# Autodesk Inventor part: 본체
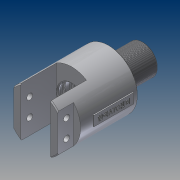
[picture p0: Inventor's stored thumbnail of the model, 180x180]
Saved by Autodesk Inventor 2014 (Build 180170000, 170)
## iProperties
Created: 2019-02
Part Number: 본체
Material: 알루미늄 6061
Document SubType Name: Modeling
Designer: 603-18
Density: 2.71 g/cm^3
Appearance: 알루미늄 - 평지
Mass: 344.106 g
Surface Area: 281.944 cm^2
Volume: 126.976 cm^3
Author: 603-18
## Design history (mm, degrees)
sketch "스케치1"
  geometry: L1 (-37, 0)-(37, 0); L2 (-37, 0)-(-37, 22); L3 (-1, 29)-(37, 29); L4 (37, 29)-(37, 0); L5 (26, 0)-(26, 16); L6 (26, 16)-(19, 16); L7 (19, 16)-(19, 14); L8 (19, 14)-(15.35, 14); L9 (15.35, 14)-(15.35, 15.2); L10 (14.55, 16)-(11.45, 16); L11 (10.65, 15.2)-(10.65, 14); L12 (10.65, 14)-(6.35, 14); L13 (5.55, 16)-(2.45, 16); L14 (1.65, 15.2)-(1.65, 14); L15 (1.65, 14)-(-1, 14); L16 (-1, 14)-(-1, 0); L17 (6.35, 14)-(6.35, 15.2); L18 (-1, 29)-(-37, 29); L19 (-37, 29)-(-37, 22); A1 r 0.8 centre (2.45, 15.2) between (2.45, 16) and (1.65, 15.2); A2 r 0.8 centre (5.55, 15.2) between (6.35, 15.2) and (5.55, 16); A3 r 0.8 centre (11.45, 15.2) between (11.45, 16) and (10.65, 15.2); A4 r 0.8 centre (14.55, 15.2) between (15.35, 15.2) and (14.55, 16); 5 further points
  constraints: 38 end point, 11 parallel, 8 point on circle, 8 tangent, 5 perpendicular, 4 centre point, 4 horizontal alignment, 4 midpoint, 3 equal radius, 2 point on line, 1 coincident, 1 collinear, 1 horizontal
  dimensions: "d0" = 74 distance of L1.start L1.end; "d1" = 20 distance between parallel lines of L16 L7; "d2" = 27 distance between parallel lines of L16 L5; "d3" = 28 diameter of L15 L1; "d5" = 58 diameter of L3 L1; "d6" = 4.7 distance between parallel lines of L17 L14; "d7" = 4.7 distance between parallel lines of L9 L11; "d9" = 7 distance between parallel lines of L5 L7 (derived); "d10" = 32 diameter of L6 L1; "d11" = 5 distance from line of L16 point (4, 16); "d12" = 9 distance of point (13, 16) point (4, 16); "d13" = 0.8 radius of A1; "d42" = 36 distance between parallel lines of L2 L16
revolve "회전1" stored, may be unused: angle "d15" = 90 deg
sketch "스케치4"
  geometry: C1 r 29 at (0, 0) reference; C2 r 14 at (0, 0)
  constraints: 1 centre point, 1 coincident
  dimensions: "d22" = 28 diameter of C2
extrude "돌출2" join sketch "스케치4" distance "d23" = 5; taper "d24" = 0 deg
sketch "스케치5"
  geometry: C1 r 14 at (0, 0) reference; C2 r 15 at (0, 0)
  constraints: 1 centre point, 1 coincident
  dimensions: "d25" = 30 diameter of C2
extrude "돌출3" join sketch "스케치5" distance "d26" = 29; taper "d27" = 0 deg
feature "스레드1" dims "d28" = 10, "d29" = 0
sketch "스케치6"
  geometry: C1 r 15 at (0, 0) reference
hole "구멍1" diameter "d32" = 12.376; stored, may be unused: countersink angle "d36" = 90 deg, drill point angle "d38" = 118 deg; dims "d30" = 10, "d31" = 10, "d33" = 18, "d34" = 4, "d35" = 2, "d37" = 22
sketch "스케치7"
  geometry: C1 r 16 at (0, 0) reference; C2 r 4 at (0, 0)
  constraints: 1 centre point, 1 coincident
  dimensions: "d39" = 8 diameter of C2
extrude "돌출4" cut sketch "스케치7" stored distance "d40" = 22; taper "d41" = 0 deg
sketch "스케치8"
  geometry: C1 r 29 at (0, 0) reference; C2 r 15 at (0, 0)
  constraints: 1 centre point, 1 coincident
  dimensions: "d43" = 30 diameter of C2
extrude "돌출5" cut sketch "스케치8" distance "d44" = 36; taper "d45" = 0 deg
sketch "스케치9"
  geometry: L1 (-22, 18.894)-(-22, -18.894); L2 (22, 18.894)-(22, -18.894); L3 (-15, 24.819)-(-15, -24.819); L4 (15, 24.819)-(15, -24.819); C1 r 15 at (0, 0) reference; A1 r 29 centre (0, 0) between (22, 18.894) and (-22, 18.894); A2 r 29 centre (0, 0) between (-22, -18.894) and (22, -18.894); A3 r 29 centre (0, 0) between (-22, 18.894) and (-22, -18.894); A4 r 29 centre (0, 0) between (22, -18.894) and (22, 18.894); 1 further point
  constraints: 12 point on circle, 8 end point, 4 centre point, 4 concentric, 3 vertical, 1 parallel, 10 other
  dimensions: "d46" = 22 distance from line of L2 C1.centre; "d47" = 22 distance from line of L1 C1.centre; "d48" = 15 distance from line of L4 C1.centre; "d49" = 15 distance from line of L3 C1.centre
extrude "돌출6" cut sketch "스케치9" distance "d50" = 36; taper "d51" = 0 deg
extrude "돌출7" cut sketch "스케치9" distance "d52" = 16; taper "d53" = 0 deg
sketch "스케치10"
  geometry: L1 (0, 0)-(0, 37.789) reference; L2 (0, 37.789)-(16, 37.789) reference; L3 (0, 18.894)-(73.46, 18.894); C1 r 3 at (9, 27.894); C2 r 3 at (9, 9.894); 1 further point
  constraints: 2 centre point, 2 end point, 1 midpoint, 1 parallel, 1 vertical alignment
  dimensions: "d54" = 6 diameter of C1; "d55" = 6 diameter of C2; "d56" = 9 distance from line of L1 C1.centre; "d57" = 18 distance of C2.centre C1.centre; "d59" = 9 distance from line of L3 C1.centre
extrude "돌출8" cut sketch "스케치10" distance "d60" = 16; taper "d61" = 0 deg
chamfer "모따기2" distance "d62" = 1; stored, may be unused: second distance "d63" = 2, angle "d64" = 45 deg
chamfer "모따기3" distance "d65" = 1; stored, may be unused: second distance "d66" = 2, angle "d67" = 45 deg
node "작업 평면1"
sketch "스케치11"
  geometry: L1 (-8, 5)-(32, 5); L2 (32, 5)-(32, -5); L3 (32, -5)-(-8, -5); L4 (-8, -5)-(-8, 5); L5 (37, 28)-(37, -28) reference; 2 further points
  constraints: 8 end point, 2 parallel, 1 horizontal, 1 horizontal alignment, 1 midpoint, 1 perpendicular
  dimensions: "d69" = 40 distance between parallel lines of L2 L4; "d70" = 5 distance between parallel lines of L5 L2; "d71" = 10 distance between parallel lines of L3 L1
extrude "돌출9" join sketch "스케치11" stored distance "d72" = 16; taper "d73" = 0 deg
sketch "스케치12"
  geometry: L1 (-8, -5)-(-8, 5) reference; L2 (32, -5)-(-8, -5) reference; 2 further points
  constraints: 1 other
  dimensions: "d74" = 20 distance from line of L1 point (12, 0); "d75" = 5 distance from line of L2 point (12, 0)
feature "엠보싱1" sketch "스케치12" dims "d76" = 0.5, "d77" = 0
chamfer "모따기4" distance "d78" = 1; stored, may be unused: second distance "d79" = 2, angle "d80" = 45 deg
node "솔리드1"
mirror "대칭1"
mirror "대칭2"
other parameters: "d68" = 29.5
